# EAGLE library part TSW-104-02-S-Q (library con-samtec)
THROUGH-HOLE .025" SQ POST HEADER Source: Samtec TSW.pdf
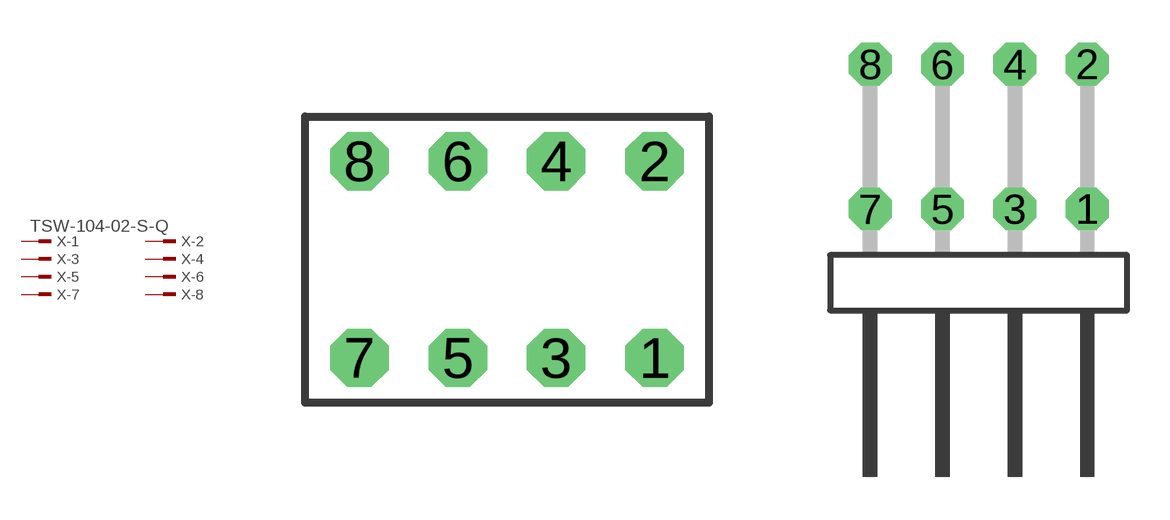
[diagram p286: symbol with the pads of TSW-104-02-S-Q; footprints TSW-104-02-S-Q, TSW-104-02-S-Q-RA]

Designator prefix X; gates -1=MPINV -2=MPIN -3=MPIN -4=MPIN -5=MPIN -6=MPIN -7=MPIN -8=MPIN

## TSW-104-02-S-Q (OC_FARNELL: unknown; OC_NEWARK: unknown)  [TSW-104-02-S-Q]
1  -1:1  pas
2  -2:1  pas
3  -3:1  pas
4  -4:1  pas
5  -5:1  pas
6  -6:1  pas
7  -7:1  pas
8  -8:1  pas

## TSW-104-02-S-Q-RA (OC_FARNELL: unknown; OC_NEWARK: unknown)  [TSW-104-02-S-Q-RA]
Pads as for TSW-104-02-S-Q

## Footprint TSW-104-02-S-Q (pad centres in mm)
THROUGH-HOLE .025" SQ POST HEADER Source: Samtec TSW.pdf
drill 1 pad 1.5 octagon: 1 3.81,-2.54; 2 3.81,2.54; 3 1.27,-2.54; 4 1.27,2.54; 5 -1.27,-2.54; 6 -1.27,2.54; 7 -3.81,-2.54; 8 -3.81,2.54

## Footprint TSW-104-02-S-Q-RA (pad centres in mm)
THROUGH-HOLE .025" SQ POST HEADER Source: Samtec TSW.pdf
drill 1 pad 1.5 octagon: 1 3.81,1.524; 2 3.81,6.604; 3 1.27,1.524; 4 1.27,6.604; 5 -1.27,1.524; 6 -1.27,6.604; 7 -3.81,1.524; 8 -3.81,6.604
